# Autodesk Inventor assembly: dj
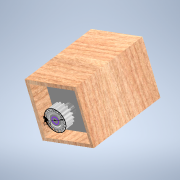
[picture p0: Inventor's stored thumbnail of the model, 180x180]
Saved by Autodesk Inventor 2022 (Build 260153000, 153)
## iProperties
Created: 2021-07
Part Number: dj
Document SubType Name: Assembly
Designer: ASUS
Author: ASUS
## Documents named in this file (4)
- C:\Users\ASUS\Downloads\dj.iam
- C:\Users\ASUS\Downloads\YN70 motor.ipt
- C:\Users\ASUS\Downloads\Part4.ipt
- C:\Users\ASUS\Downloads\motor box.ipt
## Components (3 placed, 3 different names)
1. YN70 motor:1 — Mate:2, Mate:3, Rotational:1
2. Part4:1 — Rotational:1
3. motor box:1 — Mate:2, Mate:3
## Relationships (3: Mate 2, RevoluteJoint 1)
- Mate:2: YN70 motor:1 ↔ motor box:1
- Mate:3: YN70 motor:1 ↔ motor box:1
- Rotational:1 [RevoluteJoint]: YN70 motor:1 ↔ Part4:1
